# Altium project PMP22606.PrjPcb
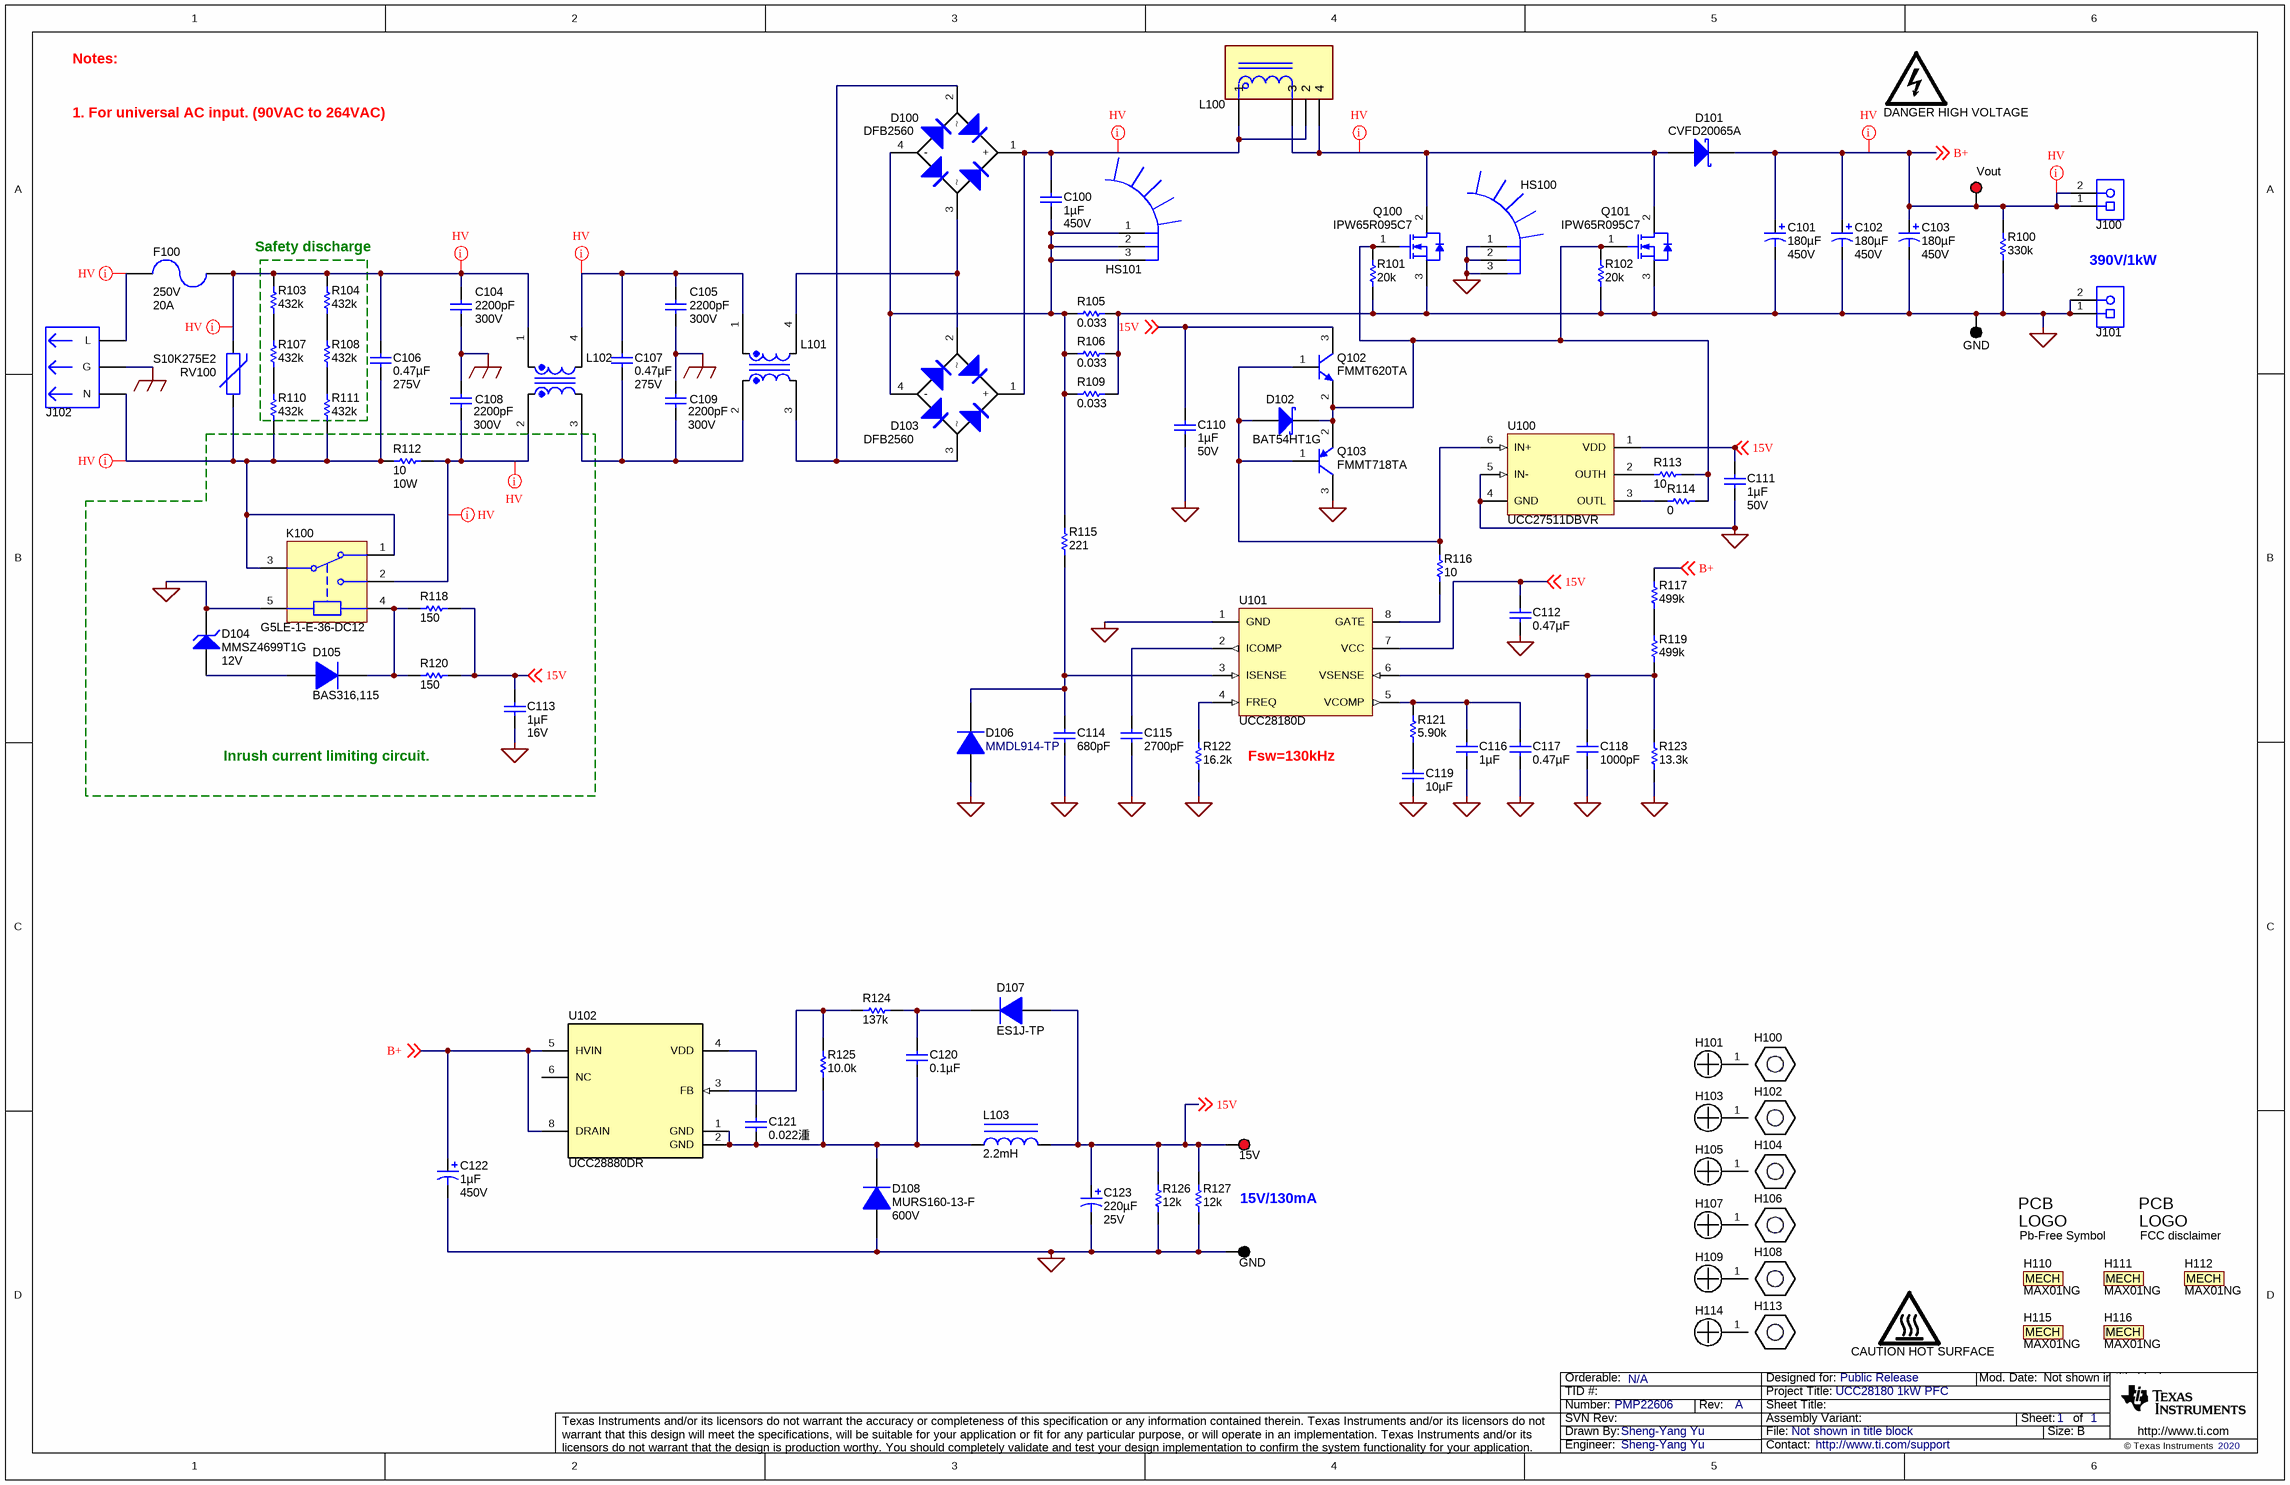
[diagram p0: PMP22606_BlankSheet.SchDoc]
CopyrightYear: 2020; EVM_Orderable: N/A; PCB_Layout: Sheng-Yang Yu; PCB_Rev: A; PRJ_Customer: Public Release; PRJ_Engineer: Sheng-Yang Yu; PRJ_Number: PMP22606; PRJ_Title: UCC28180 1kW PFC; SCH_Rev: A; TechSupport: http://www.ti.com/support
1 sheet, 105 parts. Net scope: global (net labels, ports and power ports of the same name join across sheets).
Board file: PMP22606_TID.PcbDoc

## Sheet PMP22606_BlankSheet.SchDoc
size 431 x 279 mm; Date: Not shown in title block; ApprovedBy: Not shown in title block; CheckedBy: Not shown in title block; Author: Not shown in title block; CompanyName: Not shown in title block; DrawnBy: Sheng-Yang Yu; Engineer: Not shown in title block; Organization: Not shown in title block; Address1: Not shown in title block; Address2: Not shown in title block; Address3: Not shown in title block; Address4: Not shown in title block; DocumentNumber: 1; Revision: Use project parameter SCH_Rev; SheetNumber: 1; SheetTotal: 1; PageSetup: Record=PageOptions¦CenterHorizontal=True¦CenterVertical=True¦PrintScale=1.00¦XCorrection=1.00¦YCorrection=1.00¦PrintKind=0¦BorderSize=5000000¦LeftOffset=0¦BottomOffset=0¦Orientation=2¦PaperLength=1000¦PaperWidth=1000¦Scale=100¦PaperSource=15¦PrintQuality=600¦MediaType=1¦DitherType=10¦PaperKind=Letter¦PrintScaleMode=1

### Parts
(Parts that share a designator on the sheet are numbered #1, #2 ... from top to bottom, then left to right.)
15V  5000  [Keystone5000]  (value not drawn)
C100  ValueDisplayed: 1µF  Value2: 450V  [MPK_1800x950]  (hidden comment: 450MPK105J)
C101  ValueDisplayed: 180µF  Value2: 450V  [SMQ_2200X2500]  (hidden comment: 450HXG180MEFCSN22X45)
C102  ValueDisplayed: 180µF  Value2: 450V  [SMQ_2200X2500]  (hidden comment: 450HXG180MEFCSN22X45)
C103  ValueDisplayed: 180µF  Value2: 450V  [SMQ_2200X2500]  (hidden comment: 450HXG180MEFCSN22X45)
C104  ValueDisplayed: 2200pF  Value2: 300V  [E_900x700x900]  (hidden comment: DE6E3KJ222MN3A)
C105  ValueDisplayed: 2200pF  Value2: 300V  [E_900x700x900]  (hidden comment: DE6E3KJ222MN3A)
C106  ValueDisplayed: 0.47µF  Value2: 275V  [CAPRR2250W80L2550T850H1750]  (hidden comment: ECQ-U2A474ML)
C107  ValueDisplayed: 0.47µF  Value2: 275V  [CAPRR2250W80L2550T850H1750]  (hidden comment: ECQ-U2A474ML)
C108  ValueDisplayed: 2200pF  Value2: 300V  [E_900x700x900]  (hidden comment: DE6E3KJ222MN3A)
C109  ValueDisplayed: 2200pF  Value2: 300V  [E_900x700x900]  (hidden comment: DE6E3KJ222MN3A)
C110  ValueDisplayed: 1µF  Value2: 50V  [1206]  (hidden comment: C3216X7R1H105K160AB)
C111  ValueDisplayed: 1µF  Value2: 50V  [1206]  (hidden comment: C3216X7R1H105K160AB)
C112  ValueDisplayed: 0.47µF  [0603]  (hidden comment: C0603C474K8RACTU)
C113  ValueDisplayed: 1µF  Value2: 16V  [0805_HV]  (hidden comment: 0805YD105KAT2A)
C114  ValueDisplayed: 680pF  [0603]  (hidden comment: 06031C681JAT2A)
C115  ValueDisplayed: 2700pF  [0603]  (hidden comment: 06031C272JAT2A)
C116  ValueDisplayed: 1µF  [0603]  (hidden comment: C0603C105K4PACTU)
C117  ValueDisplayed: 0.47µF  [0603]  (hidden comment: C0603C474K8RACTU)
C118  ValueDisplayed: 1000pF  [0603]  (hidden comment: CL10C102JB8NNNC)
C119  ValueDisplayed: 10µF  [1206]  (hidden comment: GRM31MR61A106KE19L)
C120  ValueDisplayed: 0.1µF  [1206]  (hidden comment: 12065C104JAT2A)
C121  ValueDisplayed: 0.022湩  [1206]  (hidden comment: 12065C223KAT2A)
C122  ValueDisplayed: 1µF  Value2: 450V  [NHG_800x1150]  (hidden comment: ECA-2WHG010)
C123  ValueDisplayed: 220µF  Value2: 25V  [Chemi-Con_800x1150]  (hidden comment: EKMG250ELL221MHB5D)
D100  DFB2560  [5S]
D101  CVFD20065A  [TO-220-2]
D102  BAT54HT1G  [sod-323]
D103  DFB2560  [5S]
D104  MMSZ4699T1G  value 12V  [SOD-123]
D105  BAS316,115  [sod-323]
D106  MMDL914-TP  [SOD-323]
D107  ES1J-TP  [SMA]
D108  MURS160-13-F  value 600V  [SMB]
F100  VAC_V: 250V  Irating_A: 20A  [FUSE_0325]  (hidden comment: 0325020.MXP)
GND#1  5001  [Keystone5001]  (value not drawn)
GND#2  5001  [Keystone5001]  (value not drawn)
H100  1902C  [Keystone_1902C]  (value not drawn)
H101  NY PMS 440 0025 PH  [NY PMS 440 0025 PH]  (value not drawn)
H102  1902C  [Keystone_1902C]  (value not drawn)
H103  NY PMS 440 0025 PH  [NY PMS 440 0025 PH]  (value not drawn)
H104  1902C  [Keystone_1902C]  (value not drawn)
H105  NY PMS 440 0025 PH  [NY PMS 440 0025 PH]  (value not drawn)
H106  1902C  [Keystone_1902C]  (value not drawn)
H107  NY PMS 440 0025 PH  [NY PMS 440 0025 PH]  (value not drawn)
H108  1902C  [Keystone_1902C]  (value not drawn)
H109  NY PMS 440 0025 PH  [NY PMS 440 0025 PH]  (value not drawn)
H110  MAX01NG  (mechanical)
H111  MAX01NG  (mechanical)
H112  MAX01NG  (mechanical)
H113  1902C  [Keystone_1902C]  (value not drawn)
H114  NY PMS 440 0025 PH  [NY PMS 440 0025 PH]  (value not drawn)
H115  MAX01NG  (mechanical)
H116  MAX01NG  (mechanical)
High_Voltage100  DANGER HIGH VOLTAGE  [IEC_HighVoltage_Small]  (no BOM)
HS100  782653B04250G  [HEATSINK_782653B04250G]  (value not drawn)
HS101  782653B04250G  [HEATSINK_782653B04250G]  (value not drawn)
J100  691214310002  [Wurth_691214310002]  (value not drawn)
J101  691214310002  [Wurth_691214310002]  (value not drawn)
J102  703W-00/54  [CONN_QUALTEK-703W-0054]  (value not drawn)
K100  G5LE-1-E-36-DC12  [RELAY_875]
L100  RLTI-1328  [FP-RLTI-1328_PTH_INDUCTOR-MFG]  (value not drawn)
L101  750318527  [7840-21-0021]  (value not drawn)
L102  750318527  [7840-21-0021]  (value not drawn)
L103  ValueDisplayed: 2.2mH  [WE-TI_8055]  (hidden comment: 744741222)
Logo100  Pb-Free Symbol  [Pb-Free_Overlay_Medium]  (no BOM)
Logo101  FCC disclaimer  [FCC_disclaimer]  (no BOM)
LOGO102  CAUTION HOT SURFACE  [IEC_HotSurface_Small]  (no BOM)
Q100  IPW65R095C7  [TO-247]
Q101  IPW65R095C7  [TO-247]
Q102  FMMT620TA  [SOT-23]
Q103  FMMT718TA  [SOT-23]
R100  ValueDisplayed: 330k  [2512]  (hidden comment: CRCW2512330KJNEG)
R101  ValueDisplayed: 20k  [1206]  (hidden comment: CRCW120620K0JNEA)
R102  ValueDisplayed: 20k  [1206]  (hidden comment: CRCW120620K0JNEA)
R103  ValueDisplayed: 432k  [1206]  (hidden comment: CRCW1206432KFKEA)
R104  ValueDisplayed: 432k  [1206]  (hidden comment: CRCW1206432KFKEA)
R105  ValueDisplayed: 0.033  [2512]  (hidden comment: RLP73M3AR033FTDF)
R106  ValueDisplayed: 0.033  [2512]  (hidden comment: RLP73M3AR033FTDF)
R107  ValueDisplayed: 432k  [1206]  (hidden comment: CRCW1206432KFKEA)
R108  ValueDisplayed: 432k  [1206]  (hidden comment: CRCW1206432KFKEA)
R109  ValueDisplayed: 0.033  [2512]  (hidden comment: RLP73M3AR033FTDF)
R110  ValueDisplayed: 432k  [1206]  (hidden comment: CRCW1206432KFKEA)
R111  ValueDisplayed: 432k  [1206]  (hidden comment: CRCW1206432KFKEA)
R112  ValueDisplayed: 10  Value2: 10W  [TWW10]  (hidden comment: TWW10J10RE)
R113  ValueDisplayed: 10  [0603]  (hidden comment: CRCW060310R0JNEAHP)
R114  ValueDisplayed: 0  [0603]  (hidden comment: CRCW06030000Z0EA)
R115  ValueDisplayed: 221  [0603]  (hidden comment: CRCW0603221RFKEA)
R116  ValueDisplayed: 10  [0603]  (hidden comment: CRCW060310R0JNEAHP)
R117  value 499k  [1206L]  (hidden comment: CRCW1206499KFKEA)
R118  ValueDisplayed: 150  [1206]  (hidden comment: CRCW1206150RJNEA)
R119  value 499k  [1206L]  (hidden comment: CRCW1206499KFKEA)
R120  ValueDisplayed: 150  [1206]  (hidden comment: CRCW1206150RJNEA)
R121  ValueDisplayed: 5.90k  [0603]  (hidden comment: CRCW06035K90FKEA)
R122  ValueDisplayed: 16.2k  [0603]  (hidden comment: CRCW060316K2FKEA)
R123  ValueDisplayed: 13.3k  [0603]  (hidden comment: CRCW060313K3FKEA)
R124  ValueDisplayed: 137k  [0603]  (hidden comment: CRCW0603137KFKEA)
R125  value 10.0k  [0603]  (hidden comment: CRCW060310K0FKEA)
R126  value 12k  [1206]  (hidden comment: CRCW120612K0JNEA)
R127  value 12k  [1206]  (hidden comment: CRCW120612K0JNEA)
RV100  S10K275E2  [VAR_S10K275E2]
U100  UCC27511DBVR  [DBV0006A_N]
U101  UCC28180D  [D0008A_N]
U102  UCC28880DR  [D0007A_N]
Vout  5000  [Keystone5000]  (value not drawn)

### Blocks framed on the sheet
Safety discharge: R103 R104 R107 R108 R110 R111
Inrush current limiting circuit.: C113 D104 D105 K100 R112 R118 R120

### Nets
GND: C101.2(-) C102.2(-) C103.2(-) C110.2 C111.2 C112.2 C113.1 C114.2 C115.2 C116.2 C117.2 C118.2 C119.2 C122.2(-) C123.2(-) D104.1(K) D106.2(A) D108.2(A) GND#1.1 GND#2.1 HS100.1 HS100.2 HS100.3 J101.1 J101.2 K100.5 Q100.3(S) Q101.3(S) Q103.3(C) R100.1 R101.1 R102.1 R105.2 R106.2 R109.2 R122.1 R123.1 R126.1 R127.1 U100.4(GND) U100.5(IN-) U101.1(GND)
PE: C104.2 C105.2 C108.1 C109.1 J102.3(G)
15V: 15V.1 C110.1 C111.1 C112.1 C113.2 C123.1(+) D107.2(A) L103.2 Q102.3(C) R118.2 R120.2 R126.2 R127.2 U100.1(VDD) U101.7(VCC) ; off-sheet 15V
B+: C101.1(+) C102.1(+) C103.1(+) C122.1(+) D101.1(K) J100.1 J100.2 R100.2 R117.2 U102.5(HVIN) U102.8(DRAIN) Vout.1 ; off-sheet B+
NetC100_1: C100.1 D100.1(+) D103.1(+) L100.1 L100.2
NetC100_2: C100.2 D100.4(-) D103.4(-) HS101.1 HS101.2 HS101.3 R105.1 R106.1 R109.1 R115.2
NetC104_1: C104.1 C106.1 F100.2 L102.1 R103.2 R104.2 RV100.2
NetC105_1: C105.1 C107.1 L101.1 L102.4
NetC106_2: C106.2 J102.2(N) K100.1 K100.3 R110.1 R111.1 R112.2 RV100.1
NetC107_2: C107.2 C109.2 L101.2 L102.3
NetC108_2: C108.2 K100.2 L102.2 R112.1
NetC114_1: C114.1 D106.1(K) R115.1 U101.3(ISENSE)
NetC115_1: C115.1 U101.2(ICOMP)
NetC116_1: C116.1 C117.1 R121.2 U101.5(VCOMP)
NetC118_1: C118.1 R119.1 R123.2 U101.6(VSENSE)
NetC119_1: C119.1 R121.1
NetC120_1: C120.1 D107.1(K) R124.2
NetC120_2: C120.2 C121.2 D108.1(K) L103.1 R125.1 U102.1(GND) U102.2(GND)
NetC121_1: C121.1 U102.4(VDD)
NetD100_2: D100.2 D103.3 L101.3
NetD100_3: D100.3 D103.2 L101.4
NetD101_2: D101.2(A) L100.3 L100.4 Q100.2(D) Q101.2(D)
NetD102_1: D102.1(K) Q100.1(G) Q101.1(G) Q102.2(E) Q103.2(E) R101.2 R102.2 R113.1 R114.2
NetD102_2: D102.2(A) Q102.1(B) Q103.1(B) R116.1 U100.6(IN+)
NetD104_2: D104.2(A) D105.2(A)
NetD105_1: D105.1(K) K100.4 R118.1 R120.1
NetF100_1: F100.1 J102.1(L)
NetR103_1: R103.1 R107.2
NetR104_1: R104.1 R108.2
NetR107_1: R107.1 R110.2
NetR108_1: R108.1 R111.2
NetR113_2: R113.2 U100.2(OUTH)
NetR114_1: R114.1 U100.3(OUTL)
NetR116_2: R116.2 U101.8(GATE)
NetR117_1: R117.1 R119.2
NetR122_2: R122.2 U101.4(FREQ)
NetR124_1: R124.1 R125.2 U102.3(FB)

Not connected (* = marked no-connect by the designer): H101 1; H103 1; H105 1; H107 1; H109 1; H114 1; U102 6(NC)

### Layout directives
net class HV: B+, NetC100_1, NetC104_1, NetC105_1, NetC106_2, NetC108_2, NetD101_2, NetF100_1

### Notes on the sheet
- Notes:
- 1. For universal AC input. (90VAC to 264VAC)
- 390V/1kW
- Fsw=130kHz
- 15V/130mA

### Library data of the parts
15V Vout = 5000: Test Point, Miniature, Red, TH; Manufacturer: Keystone; CompType: Test Point Loop; ContactFinish: Silver; Green_Lifecycle: Active; Green_REACh: Passed
C100 = 450MPK105J: CAP, Film, 1 µF, 450 V,+/- 5%, TH; Manufacturer: Rubycon; Polarized: N; CompType: Capacitor; Value: 1uF; U/M: EA; Cap_F: 0.000001; Tolerance_%: 5; VDC_V: 450; TaMin_C: -40; TaMax_C: 105; Cap_Case: 18x9.5mm; AEC Category: Q200
C101-C103 = ESMQ451VSN101MP25S: CAP ALUM 180UF 450V 20% SNAP; Manufacturer: Rubycon; Polarized: Y; CompType: Capacitor; U/M: EA; Cap_F: 0.0001; Tolerance_%: 20; Value1: Unknown; VDC_V: 450; IRMS_A: 0.93; TaMin_C: -25; TaMax_C: 85; Cap_Case: 22x25
C104 C105 C108 C109 = DE6E3KJ222MN3A: CAP, CERM, 2200 pF, 300 V, +/- 20%, E, TH, 2- Leads, Body 9x7mm, Pin Spacing 7.5mm; Manufacturer: MuRata; Polarized: N; CompType: Capacitor; Value: 2200pF; U/M: EA; Cap_F: 0.0000000022; Tolerance_%: 20; Value1: Unknown; VDC_V: 300; TaMin_C: -40; TaMax_C: 125; Cap_Case: 9x7x9mm
C106 C107 = ECQ-U2A474ML: CAP, Film, 0.47 µF, 275 V, +/- 20%, TH; Manufacturer: Panasonic; Polarized: N; CompType: Capacitor; Value: 0.47uF; U/M: EA; Cap_F: 0.00000047; Tolerance_%: 20; Value1: Unknown; VDC_V: 275; TaMin_C: -40; TaMax_C: 100; Cap_Case: Radial 25x8.5x18.5
C110 C111 = C3216X7R1H105K160AB: CAP, CERM, 1 µF, 50 V, +/- 10%, X7R, 1206; Manufacturer: TDK; Polarized: N; CompType: Capacitor; Value: 1uF; U/M: EA; Cap_F: 0.000001; Tolerance_%: 10; Value1: Unknown; VDC_V: 50; TaMin_C: -55; TaMax_C: 125
C112 C117 = C0603C474K8RACTU: CAP, CERM, 0.47 µF, 10 V, +/- 10%, X7R, 0603; Manufacturer: Kemet; Polarized: N; CompType: Capacitor; Value: 0.47uF; U/M: EA; Cap_F: 0.00000047; Tolerance_%: 10; Value1: Unknown; Value2: 10V; TaMin_C: -55; TaMax_C: 125
C113 = 0805YD105KAT2A: CAP, CERM, 1uF, 16V, +/-10%, X5R, 0805; Manufacturer: AVX; Polarized: N; CompType: Capacitor; U/M: EA; Cap_F: 0.000001; Tolerance_%: 10; ESR_Ohm: 0.012; Value1: 0.012 ohm; VDC_V: 16; TaMin_C: -55; TaMax_C: 85; Cap_Case: 0805
C114 = 06031C681JAT2A: CAP, CERM, 680 pF, 100 V,+/- 5%, X7R, 0603; Manufacturer: AVX; Polarized: N; CompType: Capacitor; Value: 680pF; U/M: EA; Cap_F: 0.00000000068; Tolerance_%: 5; ESR_ohm: 0.332; Value1: 0.332 ohm; VDC_V: 100; Value2: 100V; TaMin_C: -55; TaMax_C: 125; SizeArea_mm2: 1.28; SizeAreaWB_mm2: 4.68; SizeX_mm: 1.6; SizeY_mm: 0.8; SizeZ_mm: 1; AEC Category: Q200; Green_Lifecycle: Active; Green_REACh: Passed
C115 = 06031C272JAT2A: CAP, CERM, 2700 pF, 100 V,+/- 5%, X7R, 0603; Manufacturer: AVX; Polarized: N; CompType: Capacitor; Value: 2700pF; U/M: EA; Cap_F: 0.0000000027; Tolerance_%: 5; ESR_ohm: 0.174; Value1: 0.174 ohm; VDC_V: 100; Value2: 100V; TaMin_C: -55; TaMax_C: 125; SizeArea_mm2: 1.28; SizeAreaWB_mm2: 4.68; SizeX_mm: 1.6; SizeY_mm: 0.8; SizeZ_mm: 1; AEC Category: Q200; Green_Lifecycle: Active; Green_REACh: Passed
C116 = C0603C105K4PACTU: CAP, CERM, 1 µF, 16 V, +/- 10%, X5R, 0603; Manufacturer: Kemet; Polarized: N; CompType: Capacitor; Value: 1uF; U/M: EA; Cap_F: 0.000001; Tolerance_%: 10; Value1: Unknown; VDC_V: 16; Value2: 16V; TaMin_C: -55; TaMax_C: 85; AEC Category: Q200
C118 = CL10C102JB8NNNC: CAP, CERM, 1000 pF, 50 V, +/- 5%, X7R, 0603; Manufacturer: Samsung Electro-Mechanics; Polarized: N; CompType: Capacitor; Value: 1000pF; U/M: EA; Cap_F: 0.000000001; Tolerance_%: 5; Value1: Unknown; VDC_V: 50; Value2: 50V; TaMin_C: -55; TaMax_C: 125; AEC Category: Q200
C119 = GRM31MR61A106KE19L: CAP, CERM, 10 µF, 10 V, +/- 10%, X5R, 1206; Manufacturer: MuRata; Polarized: N; CompType: Capacitor; Value: 10uF; U/M: EA; Cap_F: 0.00001; Tolerance_%: 10; Value1: Unknown; Value2: 10V; TaMin_C: -55; TaMax_C: 85
C120 = 12065C104JAT2A: CAP, CERM, 0.1uF, 50V, +/-5%, X7R, 1206; Manufacturer: AVX; Polarized: N; CompType: Capacitor; U/M: EA; Cap_F: 0.0000001; Tolerance_%: 5; ESR_Ohm: 0.037; Value1: 0.037 ohm; VDC_V: 50; TaMin_C: -55; TaMax_C: 125
C121 = 12065C223KAT2A: CAP, CERM, 0.022uF, 50V, +/-10%, X7R, 1206; Manufacturer: AVX; Polarized: N; CompType: Capacitor; U/M: EA; Cap_F: 0.000000022; Tolerance_%: 10; ESR_Ohm: 0.079; Value1: 0.079 ohm; VDC_V: 50; TaMin_C: -55; TaMax_C: 125
C122 = ECA-2WHG010: CAP, AL, 1 µF, 450 V, +/- 20%, TH; Manufacturer: Panasonic; Polarized: Y; CompType: Capacitor; Value: 1uF; U/M: EA; Cap_F: 0.000001; Tolerance_%: 20; VDC_V: 450; IRMS_A: 0.018; TaMin_C: -25; TaMax_C: 105; Cap_Case: 8x11.5mm; SizeAreaWB_mm2: 100; SizeArea_mm2: 64; SizeX_mm: 8; SizeZ_mm: 13; AEC Category: Q200; AEC Qualified: N
C123 = EKMG250ELL221MHB5D: CAP, AL, 220 µF, 25 V, +/- 20%, TH; Manufacturer: Chemi-Con; Polarized: Y; CompType: Capacitor; Value: 220uF; U/M: EA; Cap_F: 0.00022; Tolerance_%: 20; VDC_V: 25; IRMS_A: 0.23; TaMin_C: -55; TaMax_C: 105; Cap_Case: 8x11.5mm; SizeAreaWB_mm2: 100; SizeArea_mm2: 64; SizeX_mm: 8; SizeZ_mm: 13; AEC Category: Q200; AEC Qualified: N
D100 D103 = D25XB60-7000: Bridge Rectifiers 600V 25A Glass Pass. Bridge Rectifier; Manufacturer: On Semi; CompType: Diode; U/M: EA; Vf_V: 1.05; Value1: 3.5A; Value2: 1.05V; Io_A: 3.5; Vr_V: 600; TJmax_C: 150; Type: Switching-Bridge
D101 = C3D08060A: DIODE SCHKY SIC 650V 20A TO-220; Manufacturer: Cree; U/M: EA; Vf_V: 1.8; Value2: 1.8V; Io_A: 8; Vr_V: 650; TJmax_C: 175; RJC_CperW: 1.5; Type: Schottky
D102 = BAT54HT1G: Diode, Schottky, 30 V, 0.2 A, SOD-323; Manufacturer: ON Semiconductor; U/M: EA; Vf_V: 0.35; Value: 30V; Value1: 0.2A; Value2: 0.35V; Io_A: 0.2; Vr_V: 30
D104 = MMSZ4699T1G: Diode, Zener, 12 V, 500 mW, SOD-123; Manufacturer: ON Semiconductor; SymbolCreator: a0412235; U/M: EA; Power_W: 0.5; Vz_V: 12; Value1: 0.5W; RJA_CperW: 340
D105 = BAS316,115: Diode, Ultrafast, 100 V, 0.25 A, SOD-323; Manufacturer: NXP Semiconductor; U/M: EA; Vf_V: 1.4; Value: 100V; Value1: 0.25A; Value2: 1.4V; Io_A: 0.25; Vr_V: 100; TJmax_C: 150
D106 = CMP-0029045-2: Diode, Switching, 100 V, 0.2 A, SOD-323; Manufacturer: Micro Commercial Components; Value: 100V; TJmax_C: 150°C; Vf_V: 1V; Value1: 0.2A; SizeArea_mm2: 3.645; SizeZ_mm: 1; Green_Lifecycle: Not Set; SizeY_mm: 1.35; Green_REACh: Incomplete; SizeAreaWB_mm2: 8.695; SizeX_mm: 2.7; Io_A: 200mA; AEC Category: Q101
D107 = ES1D-13-F: DIODE FAST REC 600V 1A DO214AC; Manufacturer: Diodes Inc.; U/M: EA; Io_A: 1; Vr_V: 600; TJmax_C: 150; RJC_CperW: 25; Type: Ultrafast
D108 = MURS160-13-F: Diode, Ultrafast, 600V, 1A, SMB; Manufacturer: Diodes Inc.; U/M: EA; Vf_V: 1.25; Value2: 1.25V; Io_A: 1; Vr_V: 600; TJmax_C: 150; RJC_CperW: 13
F100 = 0325020.MXP: Fuse, 20 A, 60 V, TH; Manufacturer: Littelfuse; U/M: EA; OpeningTime_100%_min: 4; OpeningTime_200%_max: 60; Interrupt_AC: 400; Rtyp_Ohm: 0.0034; MeltingTyp: 575
GND#1 GND#2 = 5001: Test Point, Miniature, Black, TH; Manufacturer: Keystone; CompType: Test Point Loop; ContactFinish: Silver; Green_Lifecycle: Active; Green_REACh: Passed
H100 H102 H104 H106 H108 H113 = 1902C: Standoff, Hex, 0.5"L #4-40 Nylon; Manufacturer: Keystone; CompType: Hardware
H101 H103 H105 H107 H109 H114 = NY PMS 440 0025 PH: Machine Screw, Round, #4-40 x 1/4, Nylon, Philips panhead; Manufacturer: B&F Fastener Supply; CompType: Hardware; SymbolCreator: codlsc; U/M: EA
H110 = MechPart: MAX Clip; Manufacturer: Aavid Thermalloy; SymbolCreator: codlsc; CompType: Mechanical; U/M: EA
H111 H112 H115 H116 = MechPart: Max Clip; Manufacturer: Aavid Thermalloy; SymbolCreator: codlsc; CompType: Mechanical; U/M: EA
High_Voltage100 = IEC_HighVoltage: IEC 61010-1 High Voltage Warning; SymbolCreator: a0412235
HS100 HS101 = 782653B04250G: HEATSINK VERT MAX CLIP, BLACK, 4.25 INCHES; Manufacturer: Aavid; SymbolCreator: a0411947
J100 J101 = 691214310002: Terminal Block, 2x1, 3.81mm, 24-16 AWG, 10A, 300VAC, TH; Manufacturer: Wurth Elektronik eiSos; SymbolCreator: a0412235; U/M: EA
J102 = 703W-00/54: AC Receptacle, 10A 250VAC; Manufacturer: Qualtek Electronics Corporation; SymbolCreator: a0799628; CompType: Connector; U/M: EA
K100 = 875B-1CC-F-S-12VDC: Relay, SPDT ( 1 Form C), 16A, 12 VDC, TH; Manufacturer: Omron; SymbolCreator: Altium; Coil Current: 30 mA; Coil Power: 360 mW; Coil Resistance: 400 ohms; Coil Voltage: 12 VDC; Turn Off Voltage (Min): 0.6 VDC; Turn On Voltage (Max): 9 VDC; Time Operate (s): 0.015; Time Release (s): 0.01
L100 = CMP-0088184-1: INDUCTOR WITH KOOL MU MAX CORE; Manufacturer: Renco Electronics; AEC Qualified: No; Symbol Name: SYM-RLTI-1328; DCR_ohm: 65mΩ
L101 L102 = 7840-21-0021: Coupled inductor, 1.68 mH,  A,  ohm, TH; Manufacturer: Wurth; SymbolCreator: a0799628; ValueDisplayed: 1.68mH; Value: 1.68mH; Ind_H: 1.7E-3
L103 = 744741101: FIXED IND 2.2MH 210MA 11 OHM TH; Manufacturer: Wurth Elektronik; CompType: Inductor; DCR_ohm: 0.39; Material: Ferrite; SizeAreaWB_mm2: 110.25; SizeArea_mm2: 72.25; SizeX_mm: 8.5; SizeZ_mm: 6; AEC Category: Q200; Green_Lifecycle: Active; Green_REACh: Passed
Logo100 = CMP-0074839-1: SymbolCreator: a0412235; Library Reference: Logo
Logo101 = CMP-0074847-1: FCC_disclaimer; Library Reference: Logo
LOGO102 = IEC_HotSurface: IEC 61010-1 Hot Surface Warning; SymbolCreator: a0412235
Q100 Q101 = IPW60R045CP: MOSFET N-CH 650V 24A TO247; Manufacturer: Infineon Technologies; Alternate Manufacturer: None; U/M: EA; ChType: N; VdsMax_V: 650; Value1: ? ohm; QgTyp_nC: 150; Vgs_V: 30; IdsMax_A: 60
Q102 = FMMT497, Zetex: TRANS NPN 80V 1.5A SOT23-3; Manufacturer: Diodes; CompType: BJT; PNP: 0; NPN: 1; Vcesat1_V: 0.2; IcRated_A: 0.5; Value1: 0.5 A; TaMin_C: -55; TaMax_C: 150; U/M: EA
Q103 = FMMT718TA, Diodes Inc.: Transistor, PNP, 20 V, 1.5 A, SOT-23; CompType: BJT; PNP: 1; NPN: 0; Vceo_V: 20; Value: 20 V; IcRated_A: 1.5; Value1: 1.5 A; HfeMax: 6; TaMin_C: -55; TaMax_C: 150; U/M: EA
R100 = CRCW2512330KJNEG: RES, 330 k, 5%, 1 W, 2512; Manufacturer: Vishay-Dale; CompType: Resistor; Value: 330k; Res_ohm: 330000; Tolerance_%: 5; Power_W: 1; Value2: 1W; VDC_V: 500; TempCo: 200 ppm/C; EIA_Code: E24; U/M: EA
R101 R102 = CRCW120620K0JNEA: RES, 20 k, 5%, 0.25 W, 1206; Manufacturer: Vishay-Dale; CompType: Resistor; Value: 20k; Res_ohm: 20000; Value_Code: 20k0; Tolerance_%: 5; Power_W: 0.25; Value2: 0.25W; VDC_V: 200; TempCo: 200 ppm/C; EIA_Code: E24; U/M: EA
R103 R104 R107 R108 R110 R111 = CRCW1206432KFKEA: RES, 432 k, 1%, 0.25 W, 1206; Manufacturer: Vishay-Dale; CompType: Resistor; Value: 432k; Res_ohm: 432000; Tolerance_%: 1; Power_W: 0.25; Value2: 0.25W; VDC_V: 200; TempCo: 100 ppm/C; EIA_Code: E96; U/M: EA
R105 R106 R109 = WSL2512R0320FEA18: RES 0.033 OHM 1% 2W 2512; Manufacturer: TE Connectivity; CompType: Resistor; Value: 0.033; Res_ohm: 0.036; Value_Code: R033; Tolerance_%: 1; Power_W: 2; TempCo: 75 ppm/C; U/M: EA
R112 = TWW10J10RE: RES, 10, 5%, 10 W, TH; Manufacturer: Ohmite; CompType: Resistor; Value: 10; Value_Code: 10R0; Tolerance_%: 5; VDC_V: 750; TempCo: 400 ppm/C; EIA_Code: E24; U/M: EA
R113 R116 = CRCW060310R0JNEAHP: RES, 10, 5%, 0.25 W, 0603; Manufacturer: Vishay-Dale; CompType: Resistor; Value: 10; Value_Code: 10R0; Tolerance_%: 5; Power_W: 0.25; Value2: 0.25W; VDC_V: 75; TempCo: 200 ppm/C; EIA_Code: E24; U/M: EA
R114 = CRCW06030000Z0EA: RES, 0, 5%, 0.1 W, 0603; Manufacturer: Vishay-Dale; CompType: Resistor; Value: 0; Value_Code: 0000; Tolerance_%: 5; Power_W: 0.1; Value2: 0.1W; VDC_V: 75; TempCo: 200 ppm/C; EIA_Code: E24; U/M: EA; AEC Category: Q200
R115 = CRCW0603221RFKEA: RES, 221, 1%, 0.1 W, 0603; Manufacturer: Vishay-Dale; CompType: Resistor; Value: 221; Value_Code: 221R; Tolerance_%: 1; Power_W: 0.1; Value2: 0.1W; VDC_V: 75; TempCo: 100 ppm/C; EIA_Code: E96; U/M: EA; AEC Category: Q200
R117 R119 = CRCW1206499KFKEA: RES, 499k ohm, 1%, 0.25W, 1206; Manufacturer: Vishay-Dale; CompType: Resistor; Res_ohm: 499000; Tolerance_%: 1; Power_W: 0.25; VDC_V: 200; TempCo: 100 ppm/C; EIA_Code: E96; U/M: EA
R118 R120 = CRCW1206150RJNEA: RES, 150, 5%, 0.25 W, 1206; Manufacturer: Vishay-Dale; CompType: Resistor; Value: 150; Value_Code: 150R; Tolerance_%: 5; Power_W: 0.25; Value2: 0.25W; VDC_V: 200; TempCo: 200 ppm/C; EIA_Code: E24; U/M: EA
R121 = CRCW06035K90FKEA: RES, 5.90 k, 1%, 0.1 W, 0603; Manufacturer: Vishay-Dale; CompType: Resistor; Value: 5.90k; Res_ohm: 5900; Value_Code: 5k90; Tolerance_%: 1; Power_W: 0.1; Value2: 0.1W; VDC_V: 75; TempCo: 100 ppm/C; EIA_Code: E96; U/M: EA
R122 = CRCW060316K2FKEA: RES, 16.2 k, 1%, 0.1 W, 0603; Manufacturer: Vishay-Dale; CompType: Resistor; Value: 16.2k; Res_ohm: 16200; Value_Code: 16k2; Tolerance_%: 1; Power_W: 0.1; Value2: 0.1W; VDC_V: 75; TempCo: 100 ppm/C; SizeArea_mm2: 1.28; SizeX_mm: 1.6; SizeY_mm: 0.8; EIA_Code: E96; U/M: EA; AEC Category: Q200; Green_Lifecycle: Active; Green_REACh: Passed
R123 = CRCW060313K3FKEA: RES, 13.3 k, 1%, 0.1 W, 0603; Manufacturer: Vishay-Dale; CompType: Resistor; Value: 13.3k; Res_ohm: 13300; Value_Code: 13k3; Tolerance_%: 1; Power_W: 0.1; Value2: 0.1W; VDC_V: 75; TempCo: 100 ppm/C; EIA_Code: E96; U/M: EA; AEC Category: Q200
R124 = CRCW0603137KFKEA: RES, 137 k, 1%, 0.1 W, 0603; Manufacturer: Vishay-Dale; CompType: Resistor; Value: 137k; Res_ohm: 137000; Tolerance_%: 1; Power_W: 0.1; Value2: 0.1W; VDC_V: 75; TempCo: 100 ppm/C; SizeArea_mm2: 1.28; SizeX_mm: 1.6; SizeY_mm: 0.8; EIA_Code: E96; U/M: EA; AEC Category: Q200; Green_Lifecycle: Active; Green_REACh: Passed
R125 = CRCW060310K0FKEA: RES, 10.0k ohm, 1%, 0.1W, 0603; Manufacturer: Vishay-Dale; CompType: Resistor; Res_ohm: 10000; Value_Code: 10k0; Tolerance_%: 1; Power_W: 0.1; VDC_V: 75; TempCo: 100 ppm/C; EIA_Code: E96; U/M: EA
R126 R127 = CRCW120612K0JNEA: RES, 12k ohm, 5%, 0.25W, 1206; Manufacturer: Vishay-Dale; CompType: Resistor; Res_ohm: 12000; Value_Code: 12k0; Tolerance_%: 5; Power_W: 0.25; VDC_V: 200; TempCo: 200 ppm/C; EIA_Code: E24; U/M: EA
RV100 = S10K275E2: Varistor 275V RMS 10MM Radial, TH; Manufacturer: EPCOS Inc; SymbolCreator: a0412235
U100 = UCC27511DBVR: Single-Channel High-Speed Low-Side Gate Driver (with 4-A Peak Source and 8-A Peak Sink), DBV0006A; Alternate PartNumber: UCC27511DBVT; Manufacturer: Texas Instruments; SymbolCreator: a0411947; CompType: IC; U/M: EA
U101 = UCC28180D: 8-PIN CONTINUOUS CONDUCTION MODE (CCM) PFC CONTROLLER, D0008A; Manufacturer: Texas Instruments; SymbolCreator: a0411947; CompType: IC; U/M: EA
U102 = CMP-0067240-2: High Voltage Switcher for Non-isolated AC/DC Conversion, D0007A (SOIC-7); Alternate Manufacturer: Texas Instruments; SizeAreaWB_mm2: 55.2; U/M: EA; SizeZ_mm: 1.75; SizeX_mm: 6.0; SizeY_mm: 4.9; SizeArea_mm2: 29.4; CompType: IC; AEC Category: Q200; AEC Qualified: N

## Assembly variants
001: not fitted D102 R113 R114 U100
